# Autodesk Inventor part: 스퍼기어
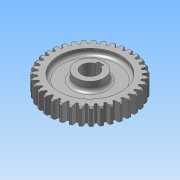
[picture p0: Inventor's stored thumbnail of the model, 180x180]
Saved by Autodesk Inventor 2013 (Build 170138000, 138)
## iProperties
Created: 2013-08
Part Number: 스퍼기어
Material: 강
Document SubType Name: Modeling
Designer: 한국산업디자인학원
Categories: <?xml version="1.0" encoding="UTF-16"?> <MemberInstance><Categories><FamilyTemplate><FamilyTemplateParameter ValueType="xs:double" Id="1" ObjectReferenceKey="da
Density: 1 g/cm^3
CustomPartVersion: 1
Author: 한국산업디자인학원
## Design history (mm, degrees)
sketch "Sketch1"
  geometry: C1 r 37 at (0, 0)
  constraints: 1 centre point
  dimensions: "d0" = 74 diameter of C1 (= da_da)
extrude "Extrusion1" new body sketch "Sketch1" distance "d1" = 15 (= da_b); taper "d2" = 0 deg
chamfer "모따기1" distance "d49" = 1; stored, may be unused: second distance "d50" = 2, angle "d51" = 45 deg
workplane "Work Plane2"
feature "피치 지름" dims "d4" = 10, "d5" = 0
workplane "Work Plane8"
workplane "Work Plane9"
feature "스퍼 기어" dims "da_b" = 15, "da_d" = 70, "da_aw" = 70, "da_da" = 74, "da_df" = 65, "da_dw" = 70, angle "da_beta" = 0 deg, "da_lefttooth" = 0, "da_righttooth" = 0
sketch "스케치3"
  geometry: C1 r 27.5 at (0, 0); C2 r 12.5 at (0, 0); A1 r 36 centre (0, 0) between (-5.215, 35.62) and (-7.633, 35.181) reference
  constraints: 2 centre point, 2 coincident
  dimensions: "d52" = 55 diameter of C1; "d54" = 25 diameter of C2
extrude "돌출2" cut sketch "스케치3" distance "d55" = 5; taper "d56" = 0 deg
sketch "스케치4"
  geometry: C1 r 12.5 at (0, 0) reference
extrude "돌출3" join sketch "스케치4" distance "d57" = 3; taper "d58" = 0 deg
sketch "스케치5"
  geometry: C1 r 12.5 at (0, 0) reference
extrude "돌출4" join sketch "스케치5" distance "d59" = 13; taper "d60" = 0 deg
sketch "스케치6"
  geometry: C1 r 12.5 at (0, 0) reference; C2 r 27.5 at (0, 0); A1 r 32.5 centre (0, 0) between (9.347, 31.127) and (7.941, 31.515) reference
  constraints: 1 centre point, 1 coincident
  dimensions: "d61" = 55 diameter of C2
extrude "돌출5" cut sketch "스케치6" distance "d63" = 5; taper "d64" = 0 deg
sketch "스케치7"
  geometry: L1 (-2.5, 7.071)-(-2.5, 9.8); L2 (-2.5, 9.8)-(2.5, 9.8); L3 (2.5, 9.8)-(2.5, 7.071); C1 r 12.5 at (0, 0) reference; A1 r 7.5 centre (0, 0) between (-2.5, 7.071) and (2.5, 7.071)
  constraints: 6 end point, 2 parallel, 2 point on circle, 1 centre point, 1 coincident, 1 perpendicular, 1 vertical
  dimensions: "d65" = 15 diameter of A1; "d67" = 5 distance of L1.end L2.end; "d68" = 17.3 dimension on A1 L2
extrude "돌출6" cut sketch "스케치7" stored distance "d69" = 5; taper "d70" = 0 deg
fillet "모깎기1" dims "d71" = 3
body "Solid1"
sketch "Sketch2"
  geometry: C1 r 37 at (0, 0) reference; C2 r 35 at (0, 0)
  constraints: 1 centre point, 1 coincident
  dimensions: "d3" = 70 diameter of C2 (= da_dw)
body "Srf1"
other parameters: "d17" = 0, "d34" = 0.8976 (computed from da_z), "d39" = 0, "d41" = 0, "d47" = 0, "d48" = 0
